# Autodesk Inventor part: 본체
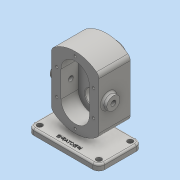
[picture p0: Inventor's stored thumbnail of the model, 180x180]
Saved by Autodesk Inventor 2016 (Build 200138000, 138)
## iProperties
Created: 2019-03
Part Number: 본체
Material: Generic
Document SubType Name: Modeling
Designer: 2-PC10
Density: 1 g/cm^3
Appearance: Default
Author: 2-PC10
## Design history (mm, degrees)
sketch "스케치1"
  geometry: L1 (-60, -36.5)-(60, -36.5); L2 (60, -36.5)-(60, 36.5); L3 (60, 36.5)-(-60, 36.5); L4 (-60, 36.5)-(-60, -36.5); L5 (-60, -36.5)-(60, 36.5); L6 (60, -36.5)-(-60, 36.5); 1 further point
  constraints: 12 end point, 2 midpoint, 2 parallel, 1 horizontal, 1 perpendicular
  dimensions: "d0" = 120 distance of L2.end L3.end; "d1" = 73 distance of L3.end L1.start
extrude "돌출1" new body sketch "스케치1" distance "d2" = 10; taper "d3" = 0 deg
node "작업 평면1"
sketch "스케치2" dims "d146" = 10
  geometry: L1 (120, 10)-(120, 0) reference; L2 (120, 0)-(0, 0) reference; L3 (0, 0)-(0, 10) reference; L4 (0, 10)-(120, 10) reference; L5 (20, 122.721)-(20, 33.279); L6 (100, 122.721)-(100, 33.279); L7 (20, 78)-(100, 78); A1 r 60 centre (60, 78) between (20, 33.279) and (100, 33.279); A2 r 60 centre (60, 78) between (100, 122.721) and (20, 122.721); 2 further points
  constraints: 6 end point, 5 point on circle, 3 midpoint, 2 centre point, 2 vertical, 1 tangent
  dimensions: "d5" = 40 distance from line of point (60, 0) L5; "d6" = 40 distance from line of L6 point (60, 0); "d7" = 78 distance between parallel lines of L2 L7; "d9" = 138 distance of point (60, 0) point (60, 138); "d10" = 60 radius of A2
extrude "돌출2" join sketch "스케치2" distance "d11" = 53; taper "d12" = 0 deg
sketch "스케치3"
  geometry: L1 (120, 10)-(120, 0) reference; L2 (120, 0)-(0, 0) reference; L3 (0, 0)-(0, 10) reference; L4 (0, 10)-(120, 10) reference; L5 (20, 33.279)-(20, 122.721) reference; L6 (100, 122.721)-(100, 33.279) reference; L7 (36, 100)-(36, 56); L8 (84, 100)-(84, 56); A1 r 60 centre (60, 78) between (20, 33.279) and (100, 33.279) reference; A2 r 60 centre (60, 78) between (100, 122.721) and (20, 122.721) reference; A3 r 24 centre (60, 100) between (84, 100) and (36, 100); A4 r 24 centre (60, 56) between (36, 56) and (84, 56); 1 further point
  constraints: 4 end point, 4 point on circle, 2 centre point, 2 tangent, 2 vertical, 1 equal radius
  dimensions: "d13" = 24 distance from line of L7 A1.centre; "d14" = 24 distance from line of L8 A1.centre; "d18" = 24 radius of A3; "d19" = 100 distance from line of L8.start L2; "d20" = 56 distance from line of L8.end L2
extrude "돌출3" cut sketch "스케치3" distance "d21" = 29; taper "d22" = 0 deg
sketch "스케치4"
  geometry: L1 (12.5, 100)-(12.5, 112.5); L2 (12.5, 112.5)-(27.5, 112.5); L3 (27.5, 112.5)-(27.5, 108.5); L4 (27.5, 108.5)-(36.5, 108.5); L5 (36.5, 108.5)-(36.5, 100); L6 (36.5, 100)-(12.5, 100); L7 (-16.5, 138)-(36.5, 138) reference; L8 (36.5, 138)-(36.5, 18) reference; L9 (36.5, 18)-(-16.5, 18) reference; L10 (-16.5, 18)-(-16.5, 32) reference; L11 (-16.5, 32)-(12.5, 32) reference; L12 (12.5, 32)-(12.5, 124) reference; L13 (12.5, 124)-(-16.5, 124) reference; L14 (-16.5, 124)-(-16.5, 138) reference; L15 (-36.5, 0)-(-36.5, 10) reference; L16 (-36.5, 10)-(36.5, 10) reference; L17 (36.5, 10)-(36.5, 0) reference; L18 (36.5, 0)-(-36.5, 0) reference; L19 (-16.5, 100)-(12.5, 100) reference; 1 further point
  constraints: 12 end point, 3 perpendicular, 2 collinear, 2 vertical, 1 parallel, 1 point on line
  dimensions: "d23" = 15 distance between parallel lines of L3 L1; "d24" = 17 diameter of L4 L6; "d25" = 25 diameter of L2 L6
revolve "회전1" sketch "스케치4" stored, may be unused: angle "d26" = 90 deg
sketch "스케치5"
  geometry: L1 (12.5, 56)-(12.5, 68.5); L2 (27.5, 68.5)-(27.5, 56); L3 (27.5, 56)-(12.5, 56); L4 (-16.5, 56)-(12.5, 56) reference; L5 (36.5, 18)-(-16.5, 18) reference; L6 (-16.5, 18)-(-16.5, 32) reference; L7 (-16.5, 32)-(12.5, 32) reference; L8 (12.5, 32)-(12.5, 87.5) reference; L9 (12.5, 87.5)-(27.5, 87.5) reference; L10 (27.5, 87.5)-(27.5, 91.5) reference; L11 (27.5, 91.5)-(36.5, 91.5) reference; L12 (36.5, 91.5)-(36.5, 18) reference; L13 (-16.5, 138)-(36.5, 138) reference; L14 (36.5, 138)-(36.5, 108.5) reference; L15 (36.5, 108.5)-(27.5, 108.5) reference; L16 (27.5, 108.5)-(27.5, 112.5) reference; L17 (27.5, 112.5)-(12.5, 112.5) reference; L18 (12.5, 112.5)-(12.5, 124) reference; L19 (12.5, 124)-(-16.5, 124) reference; L20 (-16.5, 124)-(-16.5, 138) reference; L21 (-36.5, 0)-(-36.5, 10) reference; L22 (-36.5, 10)-(36.5, 10) reference; L23 (36.5, 10)-(36.5, 0) reference; L24 (36.5, 0)-(-36.5, 0) reference; L25 (12.5, 68.5)-(27.5, 68.5); 1 further point
  constraints: 8 end point, 1 collinear, 1 horizontal, 1 perpendicular, 1 point on line, 1 vertical
  dimensions: "d29" = 15 distance between parallel lines of L2 L1; "d30" = 25 diameter of L25 L3
revolve "회전2" sketch "스케치5" stored, may be unused: angle "d31" = 90 deg
node "작업 평면2"
sketch "스케치7"
  geometry: L1 (-60, 0)-(60, 0) reference; C1 r 19 at (0, 100); 2 further points
  constraints: 1 centre point, 1 midpoint, 1 vertical alignment
  dimensions: "d36" = 38 diameter of C1; "d37" = 100 distance of point (0, 0) C1.centre
extrude "돌출5" join sketch "스케치7" distance "d38" = 17; taper "d39" = 0 deg
hole "구멍1" diameter "d42" = 28; stored, may be unused: countersink angle "d46" = 90 deg, drill point angle "d48" = 0 deg; dims "d43" = 6, "d44" = 4, "d45" = 2, "d47" = 7.3, "d49" = 10, "d50" = 10
hole "구멍2" diameter "d53" = 17; stored, may be unused: countersink angle "d57" = 90 deg, drill point angle "d59" = 118 deg; dims "d51" = 10, "d52" = 10, "d54" = 6, "d55" = 4, "d56" = 2, "d58" = 7.3
sketch "스케치8"
  geometry: L1 (122.721, -20)-(122.721, 53) reference; L2 (0, 0)-(0, 53) reference; L3 (0, 53)-(89.443, 53) reference; L4 (89.443, 53)-(89.443, 0) reference; L5 (89.443, 0)-(0, 0) reference; L6 (122.721, -20)-(112.721, -20) reference; L7 (112.721, -20)-(112.721, 53) reference; L8 (112.721, 53)-(122.721, 53) reference; L9 (122.721, 53)-(122.721, -20) reference; C1 r 11 at (44.721, 16.5); 3 further points
  constraints: 2 midpoint, 1 centre point, 1 horizontal alignment, 1 vertical alignment
  dimensions: "d60" = 22 diameter of C1
extrude "돌출6" join sketch "스케치8" distance "d61" = 8; taper "d62" = 0 deg
fillet "모깎기1" dims "d63" = 10
hole "구멍3" diameter "d66" = 9; stored, may be unused: countersink angle "d70" = 90 deg, drill point angle "d72" = 118 deg; dims "d64" = 10, "d65" = 10, "d67" = 6, "d68" = 4, "d69" = 2, "d71" = 7.3
hole "구멍4" diameter "d75" = 9; stored, may be unused: countersink angle "d79" = 90 deg, drill point angle "d81" = 118 deg; dims "d73" = 10, "d74" = 10, "d76" = 6, "d77" = 4, "d78" = 2, "d80" = 7.3
hole "구멍5" diameter "d84" = 9; stored, may be unused: countersink angle "d88" = 90 deg, drill point angle "d90" = 118 deg; dims "d82" = 10, "d83" = 10, "d85" = 6, "d86" = 4, "d87" = 2, "d89" = 7.3
hole "구멍6" diameter "d93" = 9; stored, may be unused: countersink angle "d97" = 90 deg, drill point angle "d99" = 118 deg; dims "d91" = 10, "d92" = 10, "d94" = 6, "d95" = 4, "d96" = 2, "d98" = 7.3
sketch "스케치9"
  geometry: L1 (-25, -22.5)-(25, -22.5); L2 (25, -22.5)-(25, -30.5); L3 (25, -30.5)-(-25, -30.5); L4 (-25, -30.5)-(-25, -22.5); L5 (-25, -26.5)-(25, -26.5); L6 (0, -22.5)-(0, -30.5); L7 (-60, 26.5)-(-60, -26.5) reference; L8 (-50, -36.5)-(50, -36.5) reference; 1 further point
  constraints: 4 end point, 4 midpoint, 2 other
  dimensions: "d100" = 8 distance of L6.start L6.end; "d101" = 50 distance of L5.start L5.end; "d102" = 60 distance between parallel lines of L6 L7; "d103" = 10 distance between parallel lines of L5 L8
feature "엠보싱1" sketch "스케치9" dims "d104" = 0.5, "d105" = 0
sketch "스케치10"
  geometry: L1 (-6, -6.5)-(6, -6.5); L2 (6, -6.5)-(6, 36.5); L3 (6, 36.5)-(-6, 36.5); L4 (-6, 36.5)-(-6, -6.5); L5 (18.989, -26.503)-(17.659, -26.503) reference; L6 (17.659, -26.503)-(17.659, -26.123) reference; L7 (17.659, -26.123)-(18.989, -26.123) reference; L8 (18.989, -26.123)-(18.989, -23.545) reference; L9 (18.989, -23.545)-(19.315, -23.545) reference; L10 (19.45, -23.81)-(19.45, -29.482) reference; L11 (19.45, -29.482)-(18.989, -29.482) reference; L12 (18.989, -29.482)-(18.989, -26.503) reference; L13 (-13.942, -25.852)-(-13.942, -26.246) reference; L14 (-13.942, -26.246)-(-15.061, -26.246) reference; L15 (-15.061, -26.246)-(-15.061, -27.989) reference; L16 (-15.061, -27.989)-(-15.536, -27.989) reference; L17 (-15.536, -27.989)-(-15.536, -23.498) reference; L18 (-15.536, -23.498)-(-15.231, -23.498) reference; L19 (-15.061, -23.763)-(-15.061, -25.852) reference; L20 (-15.061, -25.852)-(-13.942, -25.852) reference; L21 (-14.844, -28.939)-(-14.844, -29.319) reference; L22 (-14.844, -29.319)-(-19.193, -29.319) reference; L23 (-19.193, -29.319)-(-19.193, -27.691) reference; L24 (-19.193, -27.691)-(-18.84, -27.691) reference; L25 (-18.731, -27.908)-(-18.731, -28.939) reference; L26 (-18.731, -28.939)-(-14.844, -28.939) reference; L27 (-17.374, -24.075)-(-18.853, -24.075) reference; L28 (-18.853, -24.075)-(-18.853, -23.722) reference; L29 (-18.853, -23.722)-(-17.374, -23.722) reference; L30 (-17.374, -23.722)-(-17.374, -24.075) reference; L31 (-20.047, -24.882)-(-20.047, -24.529) reference; L32 (-20.047, -24.529)-(-16.282, -24.529) reference; L33 (-16.282, -24.529)-(-16.282, -24.882) reference; L34 (-16.282, -24.882)-(-20.047, -24.882) reference; L35 (-2.917, -29.115)-(-3.474, -27.589) reference; L36 (-3.474, -27.589)-(-5.726, -27.589) reference; L37 (-5.726, -27.589)-(-6.296, -29.115) reference; L38 (-6.296, -29.115)-(-6.777, -29.115) reference; L39 (-6.777, -29.115)-(-4.878, -24.115) reference; L40 (-4.878, -24.115)-(-4.335, -24.115) reference; L41 (-4.335, -24.115)-(-2.436, -29.115) reference; L42 (-2.436, -29.115)-(-2.917, -29.115) reference; L43 (-4.613, -24.604)-(-5.57, -27.175) reference; L44 (-5.57, -27.175)-(-3.636, -27.175) reference; L45 (-3.636, -27.175)-(-4.613, -24.604) reference; L46 (-10.095, -27.351)-(-8.284, -27.351) reference; L47 (-8.284, -27.351)-(-8.284, -29.475) reference; L48 (-8.284, -29.475)-(-8.745, -29.475) reference; L49 (-8.745, -29.475)-(-8.745, -27.725) reference; L50 (-8.745, -27.725)-(-12.578, -27.725) reference; L51 (-12.578, -27.725)-(-12.578, -27.351) reference; L52 (-12.578, -27.351)-(-10.55, -27.351) reference; L53 (-10.55, -27.351)-(-10.55, -26.13) reference; L54 (-10.55, -26.13)-(-13.311, -26.13) reference; L55 (-13.311, -26.13)-(-13.311, -25.757) reference; L56 (-13.311, -25.757)-(-8.942, -25.757) reference; L57 (-8.657, -24.088)-(-12.463, -24.088) reference; L58 (-12.463, -24.088)-(-12.463, -23.708) reference; L59 (-12.463, -23.708)-(-8.175, -23.708) reference; L60 (-8.446, -25.757)-(-7.307, -25.757) reference; L61 (-7.307, -25.757)-(-7.307, -26.13) reference; L62 (-7.307, -26.13)-(-10.095, -26.13) reference; L63 (-10.095, -26.13)-(-10.095, -27.351) reference; L64 (1.526, -24.115)-(1.526, -24.529) reference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; C1 r 4.5 at (-50, 26.5) reference; C2 r 4.5 at (50, 26.5) reference; C3 r 4.5 at (50, -26.5) reference; C4 r 4.5 at (-50, -26.5) reference; A1 r 10 centre (-50, 26.5) between (-50, 36.5) and (-60, 26.5) reference; A2 r 10 centre (50, 26.5) between (60, 26.5) and (50, 36.5) reference; A3 r 10 centre (50, -26.5) between (50, -36.5) and (60, -26.5) reference; A4 r 10 centre (-50, -26.5) between (-60, -26.5) and (-50, -36.5) reference; 62 further points
  constraints: 8 end point, 2 parallel, 1 collinear, 1 horizontal, 1 perpendicular, 76 other
  dimensions: "d106" = 43 distance of L3.end L1.start; "d107" = 6 distance from line of L4 point (0, 0); "d108" = 6 distance from line of point (0, 0) L2
extrude "돌출7" join sketch "스케치10" stored distance "d109" = 0; taper "d110" = 0 deg
sketch "스케치11"
  geometry: L1 (29, 100)-(29, 56); L2 (91, 100)-(91, 56); L3 (36, 100)-(36, 56) reference; L4 (84, 56)-(84, 100) reference; L5 (20, 33.279)-(20, 122.721) reference; L6 (100, 122.721)-(100, 33.279) reference; L7 (0, 10)-(120, 10) reference; L8 (120, 10)-(120, 0) reference; L9 (120, 0)-(0, 0) reference; L10 (0, 0)-(0, 10) reference; L11 (10, 0)-(110, 0) reference; A1 r 24 centre (60, 100) between (84, 100) and (36, 100) reference; A2 r 24 centre (60, 56) between (36, 56) and (84, 56) reference; A3 r 60 centre (60, 78) between (20, 33.279) and (100, 33.279) reference; A4 r 60 centre (60, 78) between (100, 122.721) and (20, 122.721) reference; A5 r 31 centre (60, 100) between (91, 100) and (29, 100); A6 r 31 centre (60, 56) between (29, 56) and (91, 56); 9 further points
  constraints: 6 coincident, 6 point on circle, 4 end point, 3 tangent, 2 centre point, 2 midpoint, 2 vertical, 2 vertical alignment
  dimensions: "d112" = 31 radius of A5
hole "구멍7" sketch "스케치11" at (60, 131), (60, 25), (29, 100), (91, 100), (91, 56), (29, 56) diameter "d113" = 4.134; stored, may be unused: countersink angle "d117" = 90 deg, drill point angle "d119" = 118 deg; dims "d114" = 10, "d115" = 4, "d116" = 2, "d118" = 12
hole "구멍8" diameter "d122" = 8.376; stored, may be unused: countersink angle "d126" = 90 deg, drill point angle "d128" = 118 deg; dims "d120" = 10, "d121" = 10, "d123" = 20, "d124" = 4, "d125" = 2, "d127" = 27.3
chamfer "모따기1" distance "d129" = 1; stored, may be unused: second distance "d130" = 2, angle "d131" = 45 deg
fillet "모깎기2" dims "d138" = 3
fillet "모깎기3" dims "d139" = 3
fillet "모깎기4" dims "d140" = 3
fillet "모깎기5" dims "d141" = 3
fillet "모깎기6" dims "d142" = 0.5
chamfer "모따기4" distance "d143" = 0.7; stored, may be unused: second distance "d144" = 2, angle "d145" = 30 deg
fillet "모깎기7" dims "d146" = 10
node "솔리드1"
mirror "대칭1"
mirror "대칭2"
node "절단 모서리 투영1"
node "절단 모서리 투영2"
node "절단 모서리 투영3"
node "절단 모서리 투영4"
node "절단 모서리 투영6"
node "절단 모서리 투영7"
node "절단 모서리 투영8"
other parameters: "d35" = 36.5, "d111" = 62
